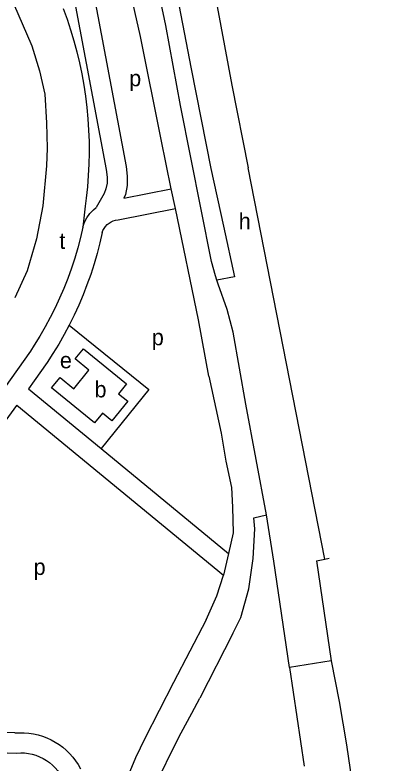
# Model space of a CAD drawing. Extents: x 157569 to 159501, y 382907 to 384670.
# Drawn here: x 159246.8 to 159337.2, y 383637.3 to 383822.5 of the extents above; entities that cross this region are included whole.
import ezdxf

# ---------------------------------------------------------------- set-up
doc = ezdxf.new("R2010")
doc.units = 0
for name, color, linetype in [('BLT_Basislijn', 7, 'Continuous'), ('BLT_Bebouwing', 7, 'Continuous'), ('BLT_Centroide', 7, 'Continuous'), ('BLT_Vlakafsluiter', 7, 'Continuous')]:
    doc.layers.add(name, color=color, linetype=linetype)

msp = doc.modelspace()

# ---------------------------------------------------------------- linework, layer by layer
at = {"layer": 'BLT_Basislijn'}
for p, q in [((159323.54, 383687.75), (159304.53, 383784.63)), ((159273.77, 383777.12), (159285.49, 383779.47)), ((159264.15, 383775.19), (159263.57, 383769.98)), ((159272.32, 383771.77), (159286.5, 383774.58)), ((159250.17, 383729.91), (159268.14, 383715.12)), ((159247.19, 383725.78), (159247.24, 383725.84)), ((159247.24, 383725.84), (159298.4, 383683.74)), ((159268.14, 383715.12), (159299.65, 383689.18)), ((159321.43, 383687.36), (159323.54, 383687.75)), ((159321.43, 383687.36), (159325.1, 383662.53)), ((159323.54, 383687.75), (159324.61, 383687.96)), ((159300.7, 383669.33), (159292.56, 383653.31)), ((159246.78, 383644.71), (159224.55, 383645.4)), ((159224.32, 383640.41), (159247.23, 383639.73))]:
    msp.add_line(p, q, dxfattribs=at)
for points in [[(159271.94, 383955.52), (159278.86, 383919.49), (159286.83, 383876.85), (159294.15, 383839.29), (159300.49, 383805.13), (159304.53, 383784.63)], [(159266.69, 383934.21), (159274, 383894.61), (159279.69, 383864.96), (159290.42, 383809.2), (159295.3, 383784.53), (159298.39, 383770.2), (159301.16, 383757.66)], [(159251.1, 383881.35), (159269.35, 383784.24), (159269.59, 383782.33), (159269.58, 383780.82), (159269.29, 383779.45), (159268.88, 383778.28), (159266.88, 383774.82)], [(159256, 383882.32), (159274.29, 383785.01), (159274.59, 383782.62), (159274.58, 383780.28), (159274.11, 383778.08), (159273.77, 383777.12)], [(159285.49, 383779.47), (159282.98, 383791.65), (159277.9, 383817.17), (159274.08, 383834.03), (159269.97, 383853.02), (159265.44, 383879.46), (159264.66, 383882.8)], [(159296.44, 383757.89), (159295.44, 383761.42), (159287.79, 383800.1), (159284.11, 383819.93), (159281.29, 383833.29), (159277.89, 383848.59), (159273.64, 383867), (159271.66, 383875.22)], [(159233.8, 383853.23), (159234.28, 383849.85), (159235.93, 383846.38), (159238.72, 383841.32), (159242.08, 383834.93), (159245.36, 383827.95), (159250.93, 383814.86), (159252.86, 383808.66), (159254.14, 383802.89), (159254.57, 383795.83), (159254.78, 383789.51), (159254.56, 383785.16), (159253.64, 383775.25), (159252.07, 383767.05), (159249.77, 383759.16), (159246.77, 383752.46)], [(159258.71, 383824.1), (159259.67, 383821.46), (159260.55, 383818.8), (159261.36, 383816.11), (159262.09, 383813.4), (159262.74, 383810.67), (159263.32, 383807.92), (159263.82, 383805.16), (159264.24, 383802.38), (159264.58, 383799.59), (159264.84, 383796.8), (159265.02, 383794), (159265.12, 383791.19), (159265.14, 383788.39), (159265.08, 383785.58), (159264.94, 383782.77), (159264.72, 383779.98), (159264.42, 383777.18), (159264.15, 383775.19)], [(159286.5, 383774.58), (159285.49, 383779.47)], [(159263.57, 383769.98), (159263.99, 383771.18), (159264.59, 383772.3), (159265.32, 383773.33), (159266.19, 383774.25), (159266.88, 383774.82)], [(159294.74, 383733.1), (159292.18, 383747.02), (159286.5, 383774.58)], [(159268.38, 383768.61), (159268.57, 383769.14), (159268.85, 383769.66), (159269.2, 383770.15), (159269.61, 383770.59), (159270.07, 383770.96), (159270.58, 383771.27), (159271.12, 383771.51), (159271.7, 383771.68), (159272.32, 383771.77)], [(159263.57, 383769.98), (159262.98, 383767.4), (159262.31, 383764.83), (159261.57, 383762.29), (159260.75, 383759.77), (159259.85, 383757.28), (159258.88, 383754.81), (159257.84, 383752.37), (159256.72, 383749.97), (159255.53, 383747.6), (159254.27, 383745.27), (159252.94, 383742.98), (159251.54, 383740.73), (159250.59, 383739.27)], [(159268.38, 383768.61), (159267.81, 383766.11), (159267.12, 383763.48), (159266.36, 383760.87), (159265.53, 383758.28), (159264.61, 383755.72), (159263.63, 383753.19), (159262.57, 383750.68), (159261.43, 383748.21), (159260.19, 383745.71)], [(159296.75, 383756.86), (159296.44, 383757.89)], [(159300.77, 383743.92), (159299.32, 383749.55), (159297.07, 383755.83), (159296.75, 383756.86)], [(159260.19, 383745.71), (159258.95, 383743.38), (159257.6, 383741.02), (159256.18, 383738.7), (159254.72, 383736.46)], [(159260.19, 383745.71), (159279.96, 383729.73), (159268.14, 383715.12)], [(159309.07, 383698.71), (159303.98, 383726.13), (159300.77, 383743.92)], [(159250.59, 383739.27), (159247.43, 383734.71), (159244.21, 383730.18), (159240.92, 383725.71), (159237.57, 383721.29), (159237.41, 383721.08)], [(159254.72, 383736.46), (159251.55, 383731.87), (159250.17, 383729.91)], [(159294.74, 383733.1), (159297.85, 383718.94), (159298.98, 383711.99), (159300.4, 383705.48), (159300.68, 383700.66), (159300.83, 383694.29), (159299.65, 383689.18)], [(159247.19, 383725.78), (159243.85, 383721.28), (159240.48, 383716.87), (159237.86, 383713.54)], [(159300.7, 383669.33), (159302.67, 383673.32), (159304.65, 383680.4), (159305.78, 383687.91), (159306.21, 383695.28), (159305.92, 383697.97), (159309.07, 383698.71)], [(159314.75, 383660.92), (159310.85, 383687.23), (159309.07, 383698.71)], [(159299.65, 383689.18), (159298.4, 383683.74)], [(159294.14, 383672.75), (159296.72, 383678.7), (159298.4, 383683.74)], [(159294.14, 383672.75), (159286.06, 383657.18), (159278.95, 383643.29), (159276.63, 383638.56), (159269.87, 383622.28)], [(159325.1, 383662.53), (159327.03, 383652.49), (159328.86, 383641.8), (159332.12, 383619.77), (159332.83, 383619.93), (159334.33, 383620.18), (159335.91, 383620.39), (159337.17, 383620.51)], [(159314.75, 383660.92), (159318.38, 383636.44)], [(159280.7, 383629.97), (159283.05, 383634.93), (159285.48, 383639.86), (159287.97, 383644.75), (159290.54, 383649.6), (159292.56, 383653.31)], [(159246.78, 383644.71), (159247.93, 383644.77), (159249.08, 383644.76), (159250.23, 383644.66), (159251.37, 383644.48), (159252.49, 383644.23), (159253.59, 383643.9), (159254.67, 383643.49), (159255.71, 383643.01), (159256.72, 383642.46), (159257.69, 383641.83), (159258.61, 383641.15), (159259.49, 383640.4), (159260.31, 383639.59), (159261.07, 383638.73), (159261.77, 383637.81), (159262.4, 383636.85), (159262.99, 383635.79)], [(159247.23, 383639.73), (159248.19, 383639.78), (159249.15, 383639.74), (159250.11, 383639.63), (159251.05, 383639.44), (159251.97, 383639.17), (159252.87, 383638.82), (159253.74, 383638.4), (159254.56, 383637.91), (159255.35, 383637.36), (159256.08, 383636.74), (159256.76, 383636.06), (159257.38, 383635.32), (159257.94, 383634.54), (159258.44, 383633.72), (159258.55, 383633.5)]]:
    msp.add_lwpolyline(points, dxfattribs=at)
at = {"layer": 'BLT_Bebouwing'}
msp.add_lwpolyline([(159263.74, 383739.87), (159274.4, 383731.17), (159272.39, 383728.71), (159274.69, 383726.84), (159270.78, 383722.04), (159268.48, 383723.92), (159266.49, 383721.48), (159255.86, 383730.16), (159257.93, 383732.72), (159261.32, 383729.96), (159265.08, 383734.55), (159261.66, 383737.32)], close=True, dxfattribs=at)
at = {"layer": 'BLT_Vlakafsluiter'}
for p, q in [((159301.16, 383757.66), (159296.75, 383756.86)), ((159325.1, 383662.53), (159314.75, 383660.92))]:
    msp.add_line(p, q, dxfattribs=at)

# ---------------------------------------------------------------- texts
at = {"layer": 'BLT_Centroide'}
for s, p in [('p', (159275.06, 383804.86)), ('h', (159302.19, 383769.45)), ('t', (159257.76, 383764.58)), ('p', (159280.66, 383740.71)), ('e', (159257.9, 383735.01)), ('b', (159266.47, 383727.8)), ('p', (159251.39, 383683.83))]:
    msp.add_text(s, height=4, dxfattribs=at).set_placement(p)

doc.saveas('drawing.dxf')
